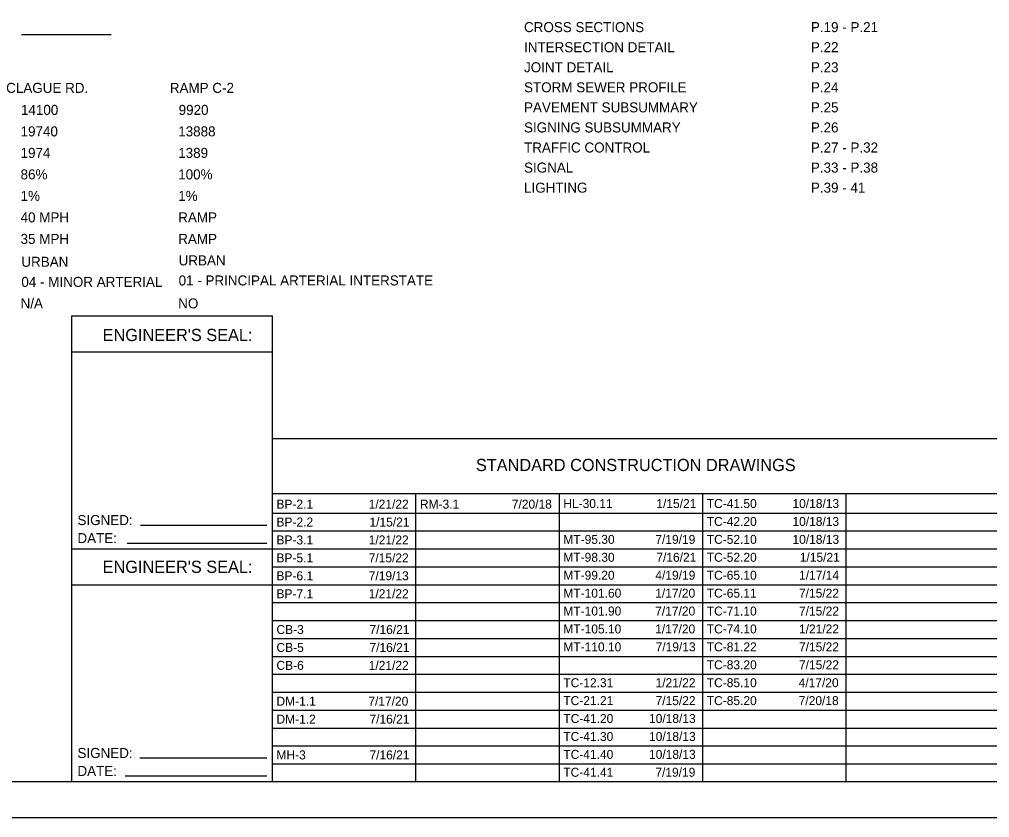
# Model space of a CAD drawing. Extents: x 0 to 34, y 0 to 22.
# Drawn here: x 7.72 to 21.25, y 0 to 11.14 of the extents above; entities that cross this region are included whole.
import ezdxf

# ---------------------------------------------------------------- set-up
doc = ezdxf.new("R2010")
doc.units = 0
for name, color, linetype in [('Default', 7, 'Continuous'), ('SH_Border', 7, 'Continuous'), ('SH_Cut_Line', 7, 'Continuous'), ('SH_Data', 7, 'Continuous'), ('SH_Text', 7, 'Continuous')]:
    doc.layers.add(name, color=color, linetype=linetype)

msp = doc.modelspace()

# ---------------------------------------------------------------- linework, layer by layer
at = {"layer": 'SH_Border'}
msp.add_lwpolyline([(1.5, 21.5), (33.5, 21.5), (33.5, 0.5), (1.5, 0.5)], close=True, dxfattribs=at)
at = {"layer": 'SH_Cut_Line'}
msp.add_lwpolyline([(0, 0), (34, 0), (34, 22), (0, 22)], close=True, dxfattribs=at)
at = {"layer": 'SH_Data'}
for p, q in [((9, 10.922), (7.75, 10.922)), ((8.45, 3.75), (8.45, 7)), ((8.45, 7), (11.25, 7)), ((11.25, 0.5), (11.25, 7)), ((8.45, 6.5), (11.25, 6.5)), ((11.25, 5.292), (24.7, 5.292)), ((11.25, 4.521), (24.7, 4.521)), ((13.25, 0.5), (13.25, 4.521)), ((15.25, 0.5), (15.25, 4.521)), ((17.25, 0.5), (17.25, 4.521)), ((19.25, 0.5), (19.25, 4.521)), ((11.25, 4.25), (22.975, 4.25)), ((11.25, 4), (22.975, 4)), ((8.45, 0.5), (8.45, 3.75)), ((8.45, 3.75), (11.25, 3.75)), ((11.25, 3.75), (24.7, 3.75)), ((11.25, 3.5), (24.7, 3.5)), ((8.45, 3.25), (11.25, 3.25)), ((11.25, 3.25), (24.7, 3.25)), ((11.25, 3), (24.7, 3)), ((11.25, 2.75), (24.7, 2.75)), ((11.25, 2.5), (24.7, 2.5)), ((11.25, 2.25), (24.7, 2.25)), ((11.25, 2), (24.7, 2)), ((11.25, 1.75), (24.7, 1.75)), ((11.25, 1.5), (24.7, 1.5)), ((11.25, 1.25), (24.7, 1.25)), ((11.25, 1), (24.7, 1)), ((11.25, 0.75), (24.7, 0.75))]:
    msp.add_line(p, q, dxfattribs=at)
at = {"layer": 'SH_Text'}
for p, q in [((9.408, 4.082), (11.171, 4.082)), ((9.222, 3.83), (11.171, 3.83)), ((9.401, 0.832), (11.171, 0.832)), ((9.193, 0.581), (11.171, 0.581))]:
    msp.add_line(p, q, dxfattribs=at)

# ---------------------------------------------------------------- texts
at = {"layer": 'Default'}
for s, height, p in [('CROSS SECTIONS', 0.14, (14.757, 10.961)), ('P.19 - P.21', 0.14, (18.757, 10.961)), ('INTERSECTION DETAIL', 0.14, (14.757, 10.681)), ('P.22', 0.14, (18.757, 10.681)), ('JOINT DETAIL', 0.14, (14.757, 10.401)), ('P.23', 0.14, (18.757, 10.401)), ('STORM SEWER PROFILE', 0.14, (14.757, 10.121)), ('P.24', 0.14, (18.757, 10.121)), ('PAVEMENT SUBSUMMARY', 0.14, (14.757, 9.841)), ('P.25', 0.14, (18.757, 9.841)), ('SIGNING SUBSUMMARY', 0.14, (14.757, 9.561)), ('P.26', 0.14, (18.757, 9.561)), ('TRAFFIC CONTROL', 0.14, (14.757, 9.281)), ('P.27 - P.32', 0.14, (18.757, 9.281)), ('SIGNAL', 0.14, (14.757, 9.001)), ('P.33 - P.38', 0.14, (18.757, 9.001)), ('LIGHTING', 0.14, (14.757, 8.721)), ('P.39 - 41', 0.14, (18.757, 8.721)), ('BP-2.1', 0.125, (11.305, 4.312)), ('1/21/22', 0.125, (12.591, 4.312)), ('RM-3.1', 0.125, (13.305, 4.312)), ('7/20/18', 0.125, (14.587, 4.312)), ('HL-30.11', 0.125, (15.305, 4.32)), ('1/15/21', 0.125, (16.602, 4.32)), ('TC-41.50', 0.125, (17.305, 4.32)), ('10/18/13', 0.125, (18.5, 4.32)), ('1/15/21', 0.125, (12.602, 4.062)), ('TC-42.20', 0.125, (17.305, 4.07)), ('10/18/13', 0.125, (18.5, 4.07)), ('BP-2.2', 0.125, (11.305, 4.062)), ('BP-3.1', 0.125, (11.305, 3.812)), ('1/21/22', 0.125, (12.591, 3.812)), ('MT-95.30', 0.125, (15.305, 3.82)), ('7/19/19', 0.125, (16.588, 3.82)), ('TC-52.10', 0.125, (17.305, 3.82)), ('10/18/13', 0.125, (18.5, 3.82)), ('BP-5.1', 0.125, (11.305, 3.562)), ('7/15/22', 0.125, (12.591, 3.562)), ('MT-98.30', 0.125, (15.305, 3.57)), ('7/16/21', 0.125, (16.602, 3.57)), ('TC-52.20', 0.125, (17.305, 3.57)), ('1/15/21', 0.125, (18.602, 3.57)), ('BP-6.1', 0.125, (11.305, 3.312)), ('7/19/13', 0.125, (12.592, 3.312)), ('MT-99.20', 0.125, (15.305, 3.32)), ('4/19/19', 0.125, (16.588, 3.32)), ('TC-65.10', 0.125, (17.305, 3.32)), ('1/17/14', 0.125, (18.592, 3.32)), ('BP-7.1', 0.125, (11.305, 3.062)), ('1/21/22', 0.125, (12.591, 3.062)), ('MT-101.60', 0.125, (15.305, 3.07)), ('1/17/20', 0.125, (16.586, 3.07)), ('TC-65.11', 0.125, (17.305, 3.07)), ('7/15/22', 0.125, (18.591, 3.07)), ('MT-101.90', 0.125, (15.305, 2.82)), ('7/17/20', 0.125, (16.586, 2.82)), ('TC-71.10', 0.125, (17.305, 2.82)), ('7/15/22', 0.125, (18.591, 2.82)), ('CB-3', 0.125, (11.305, 2.562)), ('7/16/21', 0.125, (12.602, 2.562)), ('MT-105.10', 0.125, (15.305, 2.57)), ('1/17/20', 0.125, (16.586, 2.57)), ('TC-74.10', 0.125, (17.305, 2.57)), ('1/21/22', 0.125, (18.591, 2.57)), ('CB-5', 0.125, (11.305, 2.312)), ('7/16/21', 0.125, (12.602, 2.312)), ('MT-110.10', 0.125, (15.305, 2.32)), ('7/19/13', 0.125, (16.592, 2.32)), ('TC-81.22', 0.125, (17.305, 2.32)), ('7/15/22', 0.125, (18.591, 2.32)), ('CB-6', 0.125, (11.305, 2.062)), ('1/21/22', 0.125, (12.591, 2.062)), ('TC-83.20', 0.125, (17.305, 2.07)), ('7/15/22', 0.125, (18.591, 2.07)), ('TC-12.31', 0.125, (15.305, 1.82)), ('1/21/22', 0.125, (16.591, 1.82)), ('TC-85.10', 0.125, (17.305, 1.82)), ('4/17/20', 0.125, (18.586, 1.82)), ('DM-1.1', 0.125, (11.305, 1.562)), ('7/17/20', 0.125, (12.586, 1.562)), ('TC-21.21', 0.125, (15.305, 1.57)), ('7/15/22', 0.125, (16.591, 1.57)), ('TC-85.20', 0.125, (17.305, 1.57)), ('7/20/18', 0.125, (18.587, 1.57)), ('DM-1.2', 0.125, (11.305, 1.312)), ('7/16/21', 0.125, (12.602, 1.312)), ('TC-41.20', 0.125, (15.305, 1.32)), ('10/18/13', 0.125, (16.5, 1.32)), ('TC-41.30', 0.125, (15.305, 1.07)), ('10/18/13', 0.125, (16.5, 1.07)), ('10/18/13', 0.125, (16.5, 0.82)), ('MH-3', 0.125, (11.305, 0.812)), ('7/16/21', 0.125, (12.602, 0.812)), ('TC-41.40', 0.125, (15.305, 0.82)), ('TC-41.41', 0.125, (15.305, 0.57)), ('7/19/19', 0.125, (16.588, 0.57))]:
    msp.add_text(s, height=height, dxfattribs=at).set_placement(p)
at = {"layer": 'SH_Data'}
for s, p in [('CLAGUE RD.', (7.536, 10.113)), ('RAMP C-2', (9.818, 10.113)), ('14100', (7.742, 9.806)), ('9920', (9.941, 9.806)), ('19740', (7.737, 9.506)), ('13888', (9.935, 9.506)), ('1974', (7.737, 9.206)), ('1389', (9.935, 9.206)), ('86%', (7.737, 8.906)), ('100%', (9.935, 8.906)), ('1%', (7.737, 8.606)), ('1%', (9.935, 8.606)), ('40 MPH', (7.737, 8.306)), ('RAMP', (9.935, 8.306)), ('35 MPH', (7.737, 8.006)), ('RAMP', (9.935, 8.006)), ('URBAN ', (7.748, 7.686)), ('URBAN', (9.941, 7.706)), ('04 - MINOR ARTERIAL', (7.748, 7.406)), ('01 - PRINCIPAL ARTERIAL INTERSTATE', (9.941, 7.426)), ('N/A', (7.737, 7.106)), ('NO', (9.935, 7.106))]:
    msp.add_text(s, height=0.14, dxfattribs=at).set_placement(p)
at = {"layer": 'SH_Text'}
for s, height, p in [("ENGINEER'S SEAL:", 0.17, (8.881, 6.65)), ('STANDARD CONSTRUCTION DRAWINGS', 0.17, (14.086, 4.836)), ('SIGNED:', 0.14, (8.53, 4.082)), ('DATE:', 0.14, (8.53, 3.83)), ("ENGINEER'S SEAL:", 0.17, (8.881, 3.415)), ('SIGNED:', 0.14, (8.53, 0.832)), ('DATE:', 0.14, (8.53, 0.581))]:
    msp.add_text(s, height=height, dxfattribs=at).set_placement(p)

doc.saveas('drawing.dxf')
